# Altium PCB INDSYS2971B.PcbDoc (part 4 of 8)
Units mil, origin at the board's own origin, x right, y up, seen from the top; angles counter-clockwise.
Board outline 6450 x 5820 mil, 6 copper layers (Top Layer, Int1 (PGND), Int2 (AGND), Int3 (Signal), Int4 (PGND), Bottom Layer), stack 70.536 mil thick; 787 components, 431 nets, 2530 pads, 2497 vias.
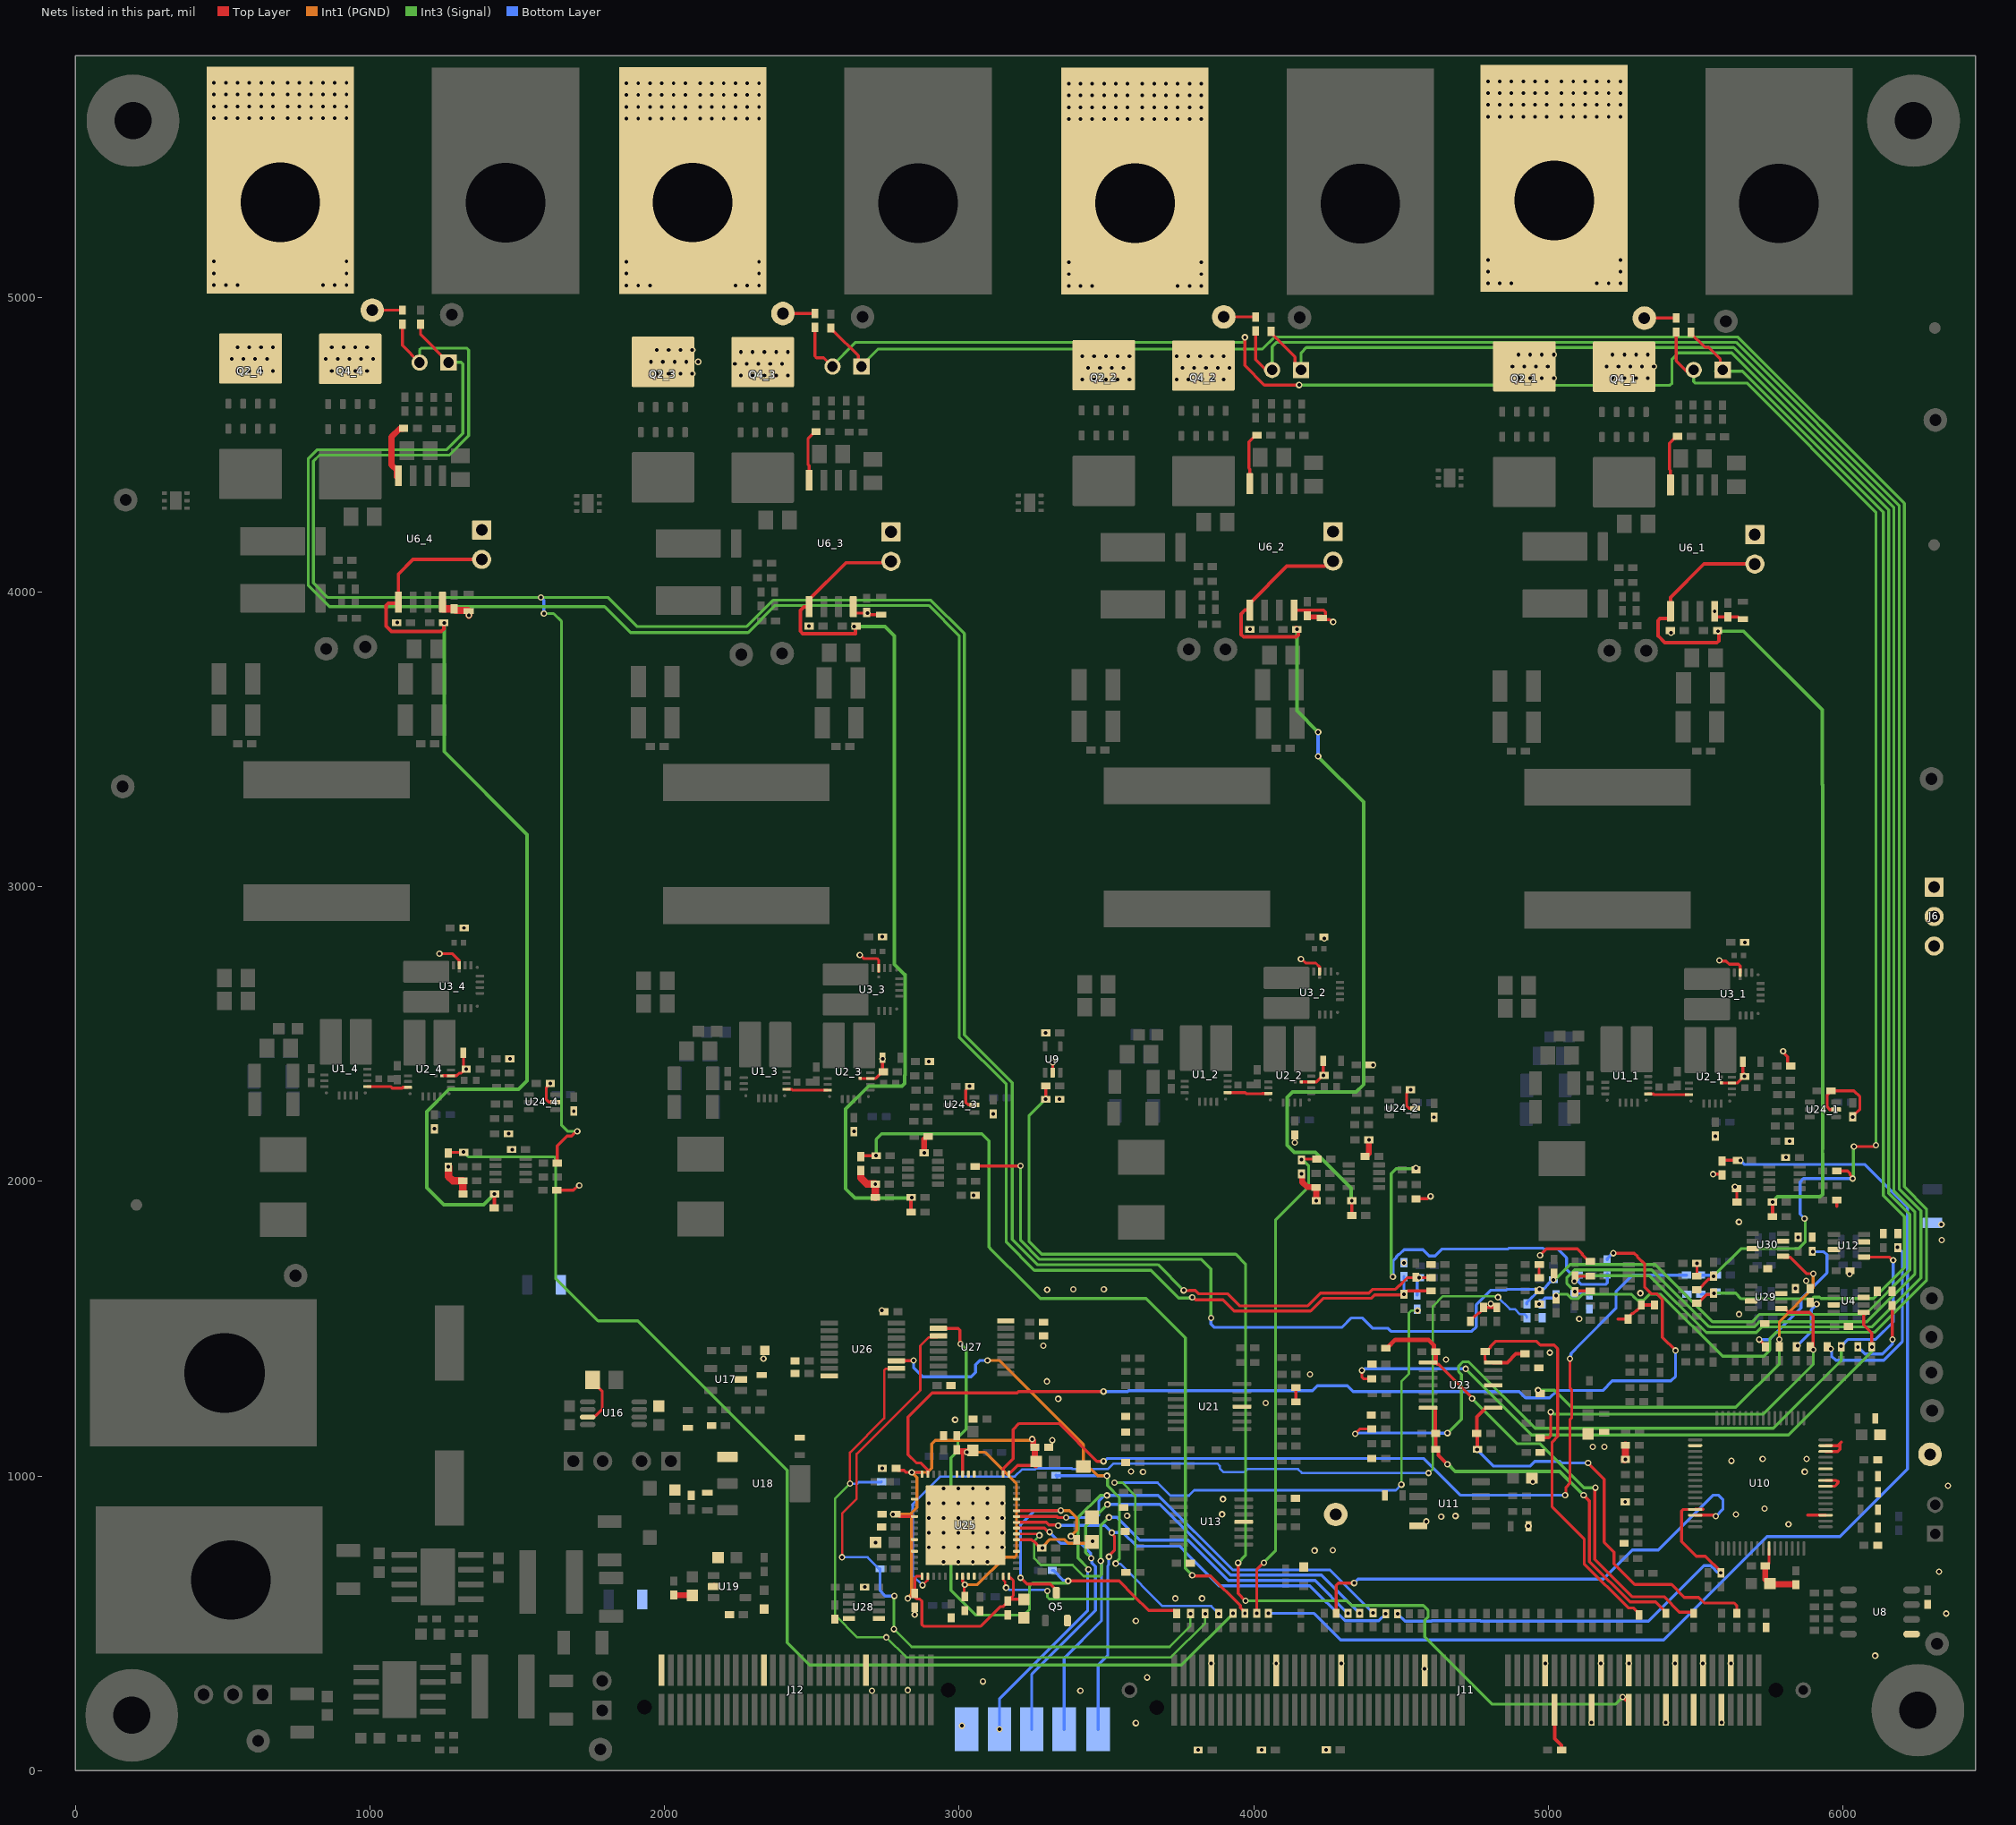
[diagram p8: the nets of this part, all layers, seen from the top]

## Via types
v1: diameter 22, hole 12.5, Top Layer to Bottom Layer, 873 vias
v2: diameter 22, hole 12, Top Layer to Bottom Layer, tented both sides, 788 vias
v3: diameter 22, hole 12, Top Layer to Bottom Layer, 586 vias
v4: diameter 22, hole 12.5, Top Layer to Bottom Layer, tented both sides, 249 vias
v5: diameter 24, hole 12, Top Layer to Bottom Layer, tented both sides, 1 vias

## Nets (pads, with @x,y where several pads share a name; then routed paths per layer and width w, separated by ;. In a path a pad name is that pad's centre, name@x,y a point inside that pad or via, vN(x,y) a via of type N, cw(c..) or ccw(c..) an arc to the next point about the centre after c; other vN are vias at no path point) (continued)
AGND: C19_1.2 C19_2.2 C19_3.2 C19_4.2 C20_1.1 C20_2.1 C20_3.1 C20_4.1 C22.2 C24_1.1 C24_2.1 C24_3.1 C24_4.1 C25.1 C27.2 C28_1.2 C28_2.2 C28_3.2 C28_4.2 C29_1.2 C29_2.2 C29_3.2 C29_4.2 C30_1.1 C30_2.1 C30_3.1 C30_4.1 C31_1.1 C31_2.1 C31_3.1 C31_4.1 C33_1.2 C33_2.2 C33_3.2 C33_4.2 C35.1 C36.1 C37.1 C38.1 C39.1 C40.1 C41.2 C43.2 C44.2 C45.2 C46.2 C47.2 C55.2 C56.2 C57.2 C58.2 C59.2 C60.2 C61.2 C62.2 C63.2 C64.1 C65.2 C66.1 C67.2 C68.1 C69.2 C70.2 C71.1 C83.1 C84.2 C85.2 C86.2 C87.2 C88.2 C89.2 C90.1 C91.2 C92.2 C93.1 C94.2 C95.2 C96.1 C98.1 C99.1 C104.1 C105.1 C109.1 C114_1.2 C114_2.2 C114_3.2 C114_4.2 C115_1.1 C115_2.1 C115_3.1 C115_4.1 C116.2 C117.1 C118.1 C119.1 C120.1 C121.1 C122.1 C123.1 C124.1 C125.1 C126.1 C127.1 C128.2 C129.1 C130.1 D1.1 D2.1 D3.1 D6.2 D7.2 J6.1 J6.2 J6.3 J9_1.1 J9_2.1 J9_3.1 J9_4.1 J11.7 J11.10 J11.13 J11.16 J11.19 J11.22 J11.29 J11.35 J11.38 J11.46 J11.47 J11.65 J11.83 J11.97 J11.111 J12.135 J12.157 J12.179 NT1_1.2 NT1_2.2 NT1_3.2 NT1_4.2 NT2_1.2 NT2_2.2 NT2_3.2 NT2_4.2 Q5.2 R10_1.2 R10_2.2 R10_3.2 R10_4.2 R11_1.2 R11_2.2 R11_3.2 R11_4.2 R16.1 R29_1.1 R29_2.1 R29_3.1 R29_4.1 R30_1.1 R30_2.1 R30_3.1 R30_4.1 R31_1.2 R31_2.2 R31_3.2 R31_4.2 R35_1.1 R35_2.1 R35_3.1 R35_4.1 R70.2 R80.2 R99.1 R101.1 R108.1 R109.1 R110.1 R114.2 R116.2 R117.2 R129.2 R130.1 R132.2 R134.2 R137.2 R139.1 R145.2 R148.2 R151.1 R156.2 R158.2 R162.1 R167.2 R168.2 R175.1 R181.1 R182.1 R189.1 R190.1 R221.1 R222.1 R224.1 R230.1 R243.1 R250.1 R254.1 R255.1 R256.1 R257.1 R258.2 R259.2 R260.2 TP7.1 TP15.1 TP16.1 U2_1.4 U2_2.4 U2_3.4 U2_4.4 U3_1.4 U3_2.4 U3_3.4 U3_4.4 U4.3 U4.7 U6_1.4 U6_2.4 U6_3.4 U6_4.4 U8.5 U9.2 U10.2 U10.26 U10.35 U10.40 U10.41 U10.43 U10.46 U10.47 U11.4 U12.3 U12.7 U13.11 U16.3 U17.2 U18.1 U19.2 U21.11 U23.11 U24_1.2 U24_2.2 U24_3.2 U24_4.2 U25.4 U25.11 U25.13 U25.23 U25.25 U25.26 U25.36 U25.45 U25.55 U25.56 U25.58 U25.65 U26.8 U27.8 U28.4 U28.5 U29.3 U29.7 U30.3 U30.7 | length 4589.8
  Top Layer w10: v2(1235.61,2773.14) 1279.05,2773.14 1302.77,2749.42 NT2_4.2@1302.77,2733.35 ; 1248.33,2359.71 1249.38,2358.65 1293.47,2358.65 1302.15,2367.33 1309.54,2367.33 1315.4,2373.19 1315.4,2374.17 1322.21,2380.98 v2(1326.14,2380.98) ; C20_4.1@1317,2387.79 C19_4.2@1317,2436.01 ; v2(1611.65,2332.2) 1598.46,2319 1598.46,2277.44 1606.98,2268.91 U24_4.2@1628.06,2268.91 ; R29_4.1@1633.62,1970.14 1690.35,1970.14 1706.21,1986 v2(1710,1986) ; U16.3@1738.62,1200.22 1758.42,1200.22 1762.28,1204.08 1765.33,1204.08 1788.26,1227 1788.26,1286.28 1755,1319.53 C91.2@1755,1326.03 ; U6_3.4@2640.39,3950.55 2640.39,3935.53 2647.2,3928.72 2688.16,3928.72 v2(2688.64,3928.24) 2688.64,3927.26 2692.2,3923.7 C30_3.1@2735.39,3923.7 ; v2(2662.53,2767.94) 2664.32,2767.94 2675.98,2756.27 2720.93,2756.27 2726.79,2750.41 U3_3.4@2726.79,2723.96 U3_3.4@2726.79,2712.95 ; NT1_3.2@2663.44,2350.14 2664.39,2349.18 U2_3.4@2698.65,2349.18 ; U2_3.4@2698.73,2349.26 2716.27,2349.26 2738.6,2371.59 C20_3.1@2742.54,2371.59 2739.81,2374.32 v2(2739.81,2415.75) ; v2(2739.52,2830.25) C24_3.1@2739.63,2830.14 ; v2(3035.67,2322.81) 3022.47,2309.61 3022.47,2268.05 3031,2259.52 U24_3.2@3052.08,2259.52 ; U9.2@3317.5,2369.43 v2(3317.5,2403.63) ; U6_2.4@4137,3938.94 4164.42,3938.94 4164.86,3938.5 4199.14,3938.5 4199.54,3938.9 4237.69,3938.9 4243.54,3933.04 C30_2.1@4243.54,3918.9 ; v2(4139.16,2132.12) R11_2.2@4139.16,2157.71 ; R158.2@4143.35,1251.83 R158.2@4143.62,1251.52 ; R167.2@4143.62,1300.14 R158.2@4143.62,1251.52 ; R158.2@4145,1250.14 R158.2@4143.62,1251.52 ; v2(4160.16,2754.32) 4163.41,2754.32 4176.76,2740.97 4210.84,2740.97 4223.4,2728.42 U3_2.4@4223.4,2712.35 ; NT1_2.2@4161.15,2337.34 4170.02,2337.34 4170.17,2337.5 4195.18,2337.5 U2_2.4@4195.26,2337.57 ; U2_2.4@4195.34,2337.65 4212.88,2337.65 4235.21,2359.98 v2(4237.18,2359.98) C20_2.1@4239.14,2359.98 4236.12,2363 C19_2.2@4236.12,2408.88 ; C30_2.1@4232,3918.9 4182,3918.9 4188.81,3912.09 C30_2.1@4232,3912.09 4237,3907.09 4258.07,3907.09 4266.24,3898.92 v2(4269.49,3898.92) v2(4269.49,3898.92) ; v2(4532.28,2311.2) 4519.08,2298 4519.08,2256.44 4527.6,2247.91 U24_2.2@4548.68,2247.91 ; R29_2.1@4551.23,1940.76 4552.05,1941.58 4589.69,1941.58 4597.13,1949.03 v2(4600.38,1949.03) ; C104.1@4734.05,1523.12 C104.1@4735.43,1524.5 ; C104.1@4735.43,1523.12 C104.1@4735.43,1524.5 ; R175.1@4780.43,1571.74 4780.43,1567.81 4765.74,1553.12 4762.57,1553.12 4752.57,1543.12 4750.11,1543.12 4735.43,1528.44 C104.1@4735.43,1524.5 ; R175.1@4781.8,1571.74 R162.1@4825.43,1571.74 ; C105.1@4969.05,1718.12 4969.05,1674.5 4970.43,1673.12 R156.2@4969.36,1672.96 ; v2(4972.23,1749.39) 4993.74,1770.9 5099.36,1770.9 5115.52,1754.74 5115.52,1751.41 5138.5,1728.44 R145.2@5142.44,1728.44 ; 5235.92,1532.4 5270.16,1532.4 C98.1@5270.92,1533.16 5270.92,1537.1 5285.6,1551.78 5288.77,1551.78 5298.77,1561.78 5301.23,1561.78 5317.44,1577.99 5317.44,1580.41 5317.44,1583.44 R151.1@5315.92,1580.41 ; v2(5416.97,3861.64) 5416.97,3859.8 5417.29,3859.8 5417.29,3869.18 R30_1.1@5416.97,3869.51 ; v2(5504.54,1721.78) 5502.44,1718.44 5504.68,1716.19 R134.2@5504.68,1678.44 ; v2(5559.53,2024.56) 5587.3,2024.56 R31_1.2@5590.34,2021.52 ; v2(5565,3934.94) 5565,3922.69 5571.81,3915.88 C31_1.1@5610,3915.88 5644.71,3915.88 5652.5,3908.09 C30_1.1@5660,3908.09 ; v4(5581.18,2750.4) 5583.48,2748.11 5603.25,2748.11 5614.38,2736.97 5645.54,2736.97 5651.4,2731.11 NT2_1.2@5651.4,2708.35 ; NT1_1.2@5588.05,2334.53 5589,2333.58 U2_1.4@5623.26,2333.58 5623.34,2333.65 5640.88,2333.65 5663.21,2355.98 C20_1.1@5667.14,2355.98 v2(5665.78,2357.35) 5660.66,2362.47 C19_1.2@5660.66,2406.14 ; C29_1.2@5640.51,1930.14 5639.96,1930.69 R35_1.1@5639.96,1975.38 R35_1.1@5642.47,1972.86 ; C55.2@5740,695.14 5741.3,695.14 5749.53,703.37 U10.26@5749.53,753.69 ; v2(5797.4,2441.79) 5797.4,2438.55 5812.62,2423.33 5812.62,2398.11 5819.43,2391.3 C114_1.2@5823.37,2391.3 ; 5880.09,866.88 U10.35@5941.46,866.88 ; U10.40@5941.46,965.3 5973.14,965.3 5982.7,974.86 5982.7,977.85 5985,980.14 ; U10.41@5941.46,984.99 5977.64,984.99 5981.75,980.88 5985,980.88 ; U10.46@5941.46,1083.41 5983.27,1083.41 5990,1090.14 5990,1110.14 ; U10.47@5941.46,1103.1 5982.95,1103.1 5990,1110.14 ; U24_1.2@5976.68,2243.91 5955.6,2243.91 5947.08,2252.44 5947.08,2294 C115_1.1@5960.28,2307.2 6038.05,2307.2 6058.15,2287.1 6058.15,2244.94 6042.73,2229.53 6040.28,2229.53 6033.46,2222.71 v2(6033.46,2218.78) ; R29_1.1@5979.23,1936.76 5979.42,1936.56 5979.42,1915.1 ; 5995,1115.14 5990,1110.14
  Top Layer w12: J11.46@5021.34,206.29 5021.34,108.81 5044.96,85.18 C37.1@5044.96,70.14 ; R151.1@5317.44,1580.41 R139.1@5360.92,1580.41
  Top Layer w20: C93.1@2031.2,596.13 2031.9,595.42 C92.2@2092.17,595.42 ; U19.2@2166.04,624.71 U19.2@2167.85,626.52 ; D3.1@2332.31,543.09 D3.1@2338.06,548.84 ; v2(2881.14,2096.75) 2881.14,2143.02 2890.45,2152.32 C28_3.2@2894.38,2152.32 ; R31_2.2@4162.34,2021.59 v2(4162.34,2025.52) 4164.15,2023.71 4164.15,1998.12 4181.08,1981.19 4210.15,1981.19 R35_2.1@4211.96,1979.38 4212.23,1979.11 4212.23,1934.42 v2(4212.51,1934.14) ; C33_2.2@4377.75,2085.14 4381.69,2085.14 4390.99,2094.45 v2(4390.99,2140.71) ; C55.2@5736.77,694.56 5736.77,649.24 C56.2@5750.87,635.14 ; C56.2@5752.52,634.48 C56.2@5750.87,635.14 ; R101.1@5841.02,630.93 5839.25,632.71 5757.44,632.71 5755,635.14 C56.2@5750.87,635.14
  Top Layer w25: U6_4.4@1246.1,3965.85 1246.1,3943.6 1246.79,3942.91 1284.91,3942.91 C31_4.1@1285,3942.82 1290.29,3937.53 1332.5,3937.53 C30_4.1@1335,3935.03 v2(1335,3921.72) ; v2(1265.34,2050.43) 1266.02,2049.74 1266.02,2016.69 1280.67,2002.04 1314.68,2002.04 R35_4.1@1314.96,2002.32 1315.23,2002.04 1315.23,1957.36 C29_4.2@1315.51,1957.08 ; R31_3.2@2665.73,2037.13 2665.73,2011.54 2685.59,1991.68 2714.66,1991.68 v2(2715.35,1990.99) 2715.62,1990.71 2715.62,1946.03 C29_3.2@2715.9,1945.75 ; R109.1@5260,1055.14 v2(5261.62,1056.76) R109.1@5261.93,1056.76 R110.1@5261.93,1104.56
  other v2: 3811.38,70.14 4026.38,70.14 4246.38,70.64 3009.68,152.04 3599.79,161.14 5146.9,162.98 5399.29,162.98 5588.27,162.98 2703.95,271.15 3411.2,271.23 2825.85,273.21 3080.43,302.45 3638.1,316.14 4580.39,344.99 3855.98,363.41 4076.46,363.41 4297.01,363.41 4989.84,363.41 5178.82,363.41 5273.6,363.41 5430.79,363.41 5525.28,363.64 5619.76,363.41 6110,390.13 3599.79,508.08 2849.09,529.52 6350.7,533.06 3733.94,584.67 3824.49,584.67 2679.44,622.93 6326.58,675.35 2946.54,707.93 2996.54,707.93 3046.54,707.93 3096.54,707.93 4206.7,746.97 4268.81,747.71 2896.54,757.93 2946.54,757.93 2996.54,757.93 3046.54,757.93 3096.54,757.93 3146.54,757.93 2716.41,774.29 2896.54,807.93 2946.54,807.93 2996.54,807.93 3046.54,807.93 3096.54,807.93 3146.54,807.93 5815.66,836.12 4586.11,845.74 2896.54,857.93 2946.54,857.93 2996.54,857.93 3046.54,857.93 3096.54,857.93 3146.54,857.93 4636.54,862.23 4685.17,864.33 3570.32,865.2 3892.59,870.14 5636.89,869.85 5734.36,889.33 2896.54,907.93 2946.54,907.93 2996.54,907.93 3046.54,907.93 3096.54,907.93 3146.54,907.93 5261.18,911.8 3895.58,921.85 2946.54,957.93 2996.54,957.93 3046.54,957.93 3096.54,957.93 6357.51,967.16 4947.16,981.14 3624.07,1013.71 5870.63,1014.51 3583.67,1015.52 2738.97,1026.11 5621.57,1051.27 5727.64,1057.91 5877.45,1057.91 5150.92,1099.05 5190.47,1099.05 3316.22,1121.16 2985.94,1190.89 4040.78,1247.64 3336.37,1262.08 3298.1,1321.39 4191.01,1345.14 4652.92,1394.83 2335.68,1398.27 5005.01,1418.65 3285.84,1442.07 5105.01,1533.16 5647.98,1549.24 2737.76,1562.54 4804.93,1584.62 5312.89,1620.37 3298.63,1631.84 3387.8,1633.84 3491.39,1633.84 5839.5,1636.08 5875.72,1662.65 6022.58,1684.9 4510,1723.77 6336.08,1800.82 5848.1,1810.18 6335.01,1853.89 5647.22,1862.27 3048.62,1952.37 5633.68,1981.73 5807.72,2081.15 1482.72,2108.08 5818.99,2136.71 5567.16,2153.71 1470.37,2161.71 2642.55,2169.32 1218.54,2178.71 4612.28,2217.66 3115.67,2229.27 1691.65,2238.66 3341.12,2278.72 4405,2395.3 2896.79,2406.91 1474.75,2416.3 3293.88,2503.72 5667.18,2811.46 4240,2825.14 1318.95,2860.14 3987,3873.5 2490.39,3885.11 1091.97,3896.44
  other v5: 4932.71,829.49
BATP_1: J7_1.1 Q2_1.5 Q2_1.6 Q2_1.7 Q2_1.8 Q2_1.9@4919,4766.07 Q4_1.5 Q4_1.6 Q4_1.7 Q4_1.8 Q4_1.9@5257.36,4765.07 R19_1.1 T3_1.1 TP5_1.1 | length 108.5
  Top Layer w10: TP5_1.1@5326.24,4930.14 R19_1.1@5434.69,4930.11
  other v1: 4898.39,4726.14 4938.39,4726.14 4978.39,4726.14 5018.39,4726.14 5218.39,4726.14 5258.39,4726.14 5298.39,4726.14 5338.39,4726.14 4878.39,4766.14 4918.39,4766.14 4958.39,4766.14 4998.39,4766.14 5198.39,4766.14 5238.39,4766.14 5278.39,4766.14 5318.39,4766.14 5358.39,4766.14 4898.39,4806.14 4938.39,4806.14 4978.39,4806.14 5018.39,4806.14 5218.39,4806.14 5258.39,4806.14 5298.39,4806.14 5338.39,4806.14
  other v3: 4795,5047.77 4835,5047.77 4875,5047.77 5165,5047.77 5205,5047.77 5245,5047.77 4795,5087.77 5245,5087.77 4795,5127.77 5245,5127.77 4795,5614.03 4835,5614.03 4875,5614.03 4915,5614.03 4955,5614.03 4995,5614.03 5045,5614.03 5085,5614.03 5125,5614.03 5165,5614.03 5205,5614.03 5245,5614.03 4795,5654.03 4835,5654.03 4875,5654.03 4915,5654.03 4955,5654.03 4995,5654.03 5045,5654.03 5085,5654.03 5125,5654.03 5165,5654.03 5205,5654.03 5245,5654.03 4795,5694.03 4835,5694.03 4875,5694.03 4915,5694.03 4955,5694.03 4995,5694.03 5045,5694.03 5085,5694.03 5125,5694.03 5165,5694.03 5205,5694.03 5245,5694.03 4795,5734.03 4835,5734.03 4875,5734.03 4915,5734.03 4955,5734.03 4995,5734.03 5045,5734.03 5085,5734.03 5125,5734.03 5165,5734.03 5205,5734.03 5245,5734.03
BATP_2: J7_2.1 Q2_2.5 Q2_2.6 Q2_2.7 Q2_2.8 Q2_2.9@3491,4770.07 Q4_2.5 Q4_2.6 Q4_2.7 Q4_2.8 Q4_2.9@3829.36,4769.07 R19_2.1 T3_2.1 TP5_2.1 | length 108.5
  Top Layer w10: TP5_2.1@3898.24,4934.14 R19_2.1@4006.69,4934.11
  other v1: 3418,4721.14 3458,4721.14 3498,4721.14 3538,4721.14 3578,4721.14 3738,4721.14 3778,4721.14 3818,4721.14 3858,4721.14 3898,4721.14 3438,4761.14 3478,4761.14 3518,4761.14 3558,4761.14 3758,4761.14 3798,4761.14 3838,4761.14 3878,4761.14 3918,4761.14 3418,4801.14 3458,4801.14 3498,4801.14 3538,4801.14 3578,4801.14 3738,4801.14 3778,4801.14 3818,4801.14 3858,4801.14 3898,4801.14
  other v3: 3371.97,5039.45 3411.97,5039.45 3451.97,5039.45 3741.97,5039.45 3781.97,5039.45 3821.97,5039.45 3371.97,5079.45 3821.97,5079.45 3371.97,5119.45 3821.97,5119.45 3371.97,5605.71 3411.97,5605.71 3451.97,5605.71 3491.97,5605.71 3531.97,5605.71 3571.97,5605.71 3621.97,5605.71 3661.97,5605.71 3701.97,5605.71 3741.97,5605.71 3781.97,5605.71 3821.97,5605.71 3371.97,5645.71 3411.97,5645.71 3451.97,5645.71 3491.97,5645.71 3531.97,5645.71 3571.97,5645.71 3621.97,5645.71 3661.97,5645.71 3701.97,5645.71 3741.97,5645.71 3781.97,5645.71 3821.97,5645.71 3371.97,5685.71 3411.97,5685.71 3451.97,5685.71 3491.97,5685.71 3531.97,5685.71 3571.97,5685.71 3621.97,5685.71 3661.97,5685.71 3701.97,5685.71 3741.97,5685.71 3781.97,5685.71 3821.97,5685.71 3371.97,5725.71 3411.97,5725.71 3451.97,5725.71 3491.97,5725.71 3531.97,5725.71 3571.97,5725.71 3621.97,5725.71 3661.97,5725.71 3701.97,5725.71 3741.97,5725.71 3781.97,5725.71 3821.97,5725.71
BATP_3: J7_3.1 Q2_3.5 Q2_3.6 Q2_3.7 Q2_3.8 Q2_3.9@1994.39,4781.68 Q4_3.5 Q4_3.6 Q4_3.7 Q4_3.8 Q4_3.9@2332.75,4780.68 R19_3.1 T3_3.1 TP5_3.1 | length 108.5
  Top Layer w10: TP5_3.1@2401.63,4945.75 R19_3.1@2510.05,4945.75
  other v1: 2258.57,4735.28 2298.57,4735.28 2338.57,4735.28 2378.57,4735.28 2418.57,4735.28 1973.78,4741.75 2013.78,4741.75 2053.78,4741.75 2093.78,4741.75 2238.57,4775.28 2278.57,4775.28 2318.57,4775.28 2358.57,4775.28 2398.57,4775.28 1953.78,4781.75 1993.78,4781.75 2033.78,4781.75 2073.78,4781.75 2113.78,4781.75 2258.57,4815.28 2298.57,4815.28 2338.57,4815.28 2378.57,4815.28 2418.57,4815.28 1973.78,4821.75 2013.78,4821.75 2053.78,4821.75 2093.78,4821.75
  other v3: 1870.39,5041.05 1910.39,5041.05 1950.39,5041.05 2240.39,5041.05 2280.39,5041.05 2320.39,5041.05 1870.39,5081.05 2320.39,5081.05 1870.39,5121.05 2320.39,5121.05 1870.39,5607.32 1910.39,5607.32 1950.39,5607.32 1990.39,5607.32 2030.39,5607.32 2070.39,5607.32 2120.39,5607.32 2160.39,5607.32 2200.39,5607.32 2240.39,5607.32 2280.39,5607.32 2320.39,5607.32 1870.39,5647.32 1910.39,5647.32 1950.39,5647.32 1990.39,5647.32 2030.39,5647.32 2070.39,5647.32 2120.39,5647.32 2160.39,5647.32 2200.39,5647.32 2240.39,5647.32 2280.39,5647.32 2320.39,5647.32 1870.39,5687.32 1910.39,5687.32 1950.39,5687.32 1990.39,5687.32 2030.39,5687.32 2070.39,5687.32 2120.39,5687.32 2160.39,5687.32 2200.39,5687.32 2240.39,5687.32 2280.39,5687.32 2320.39,5687.32 1870.39,5727.32 1910.39,5727.32 1950.39,5727.32 1990.39,5727.32 2030.39,5727.32 2070.39,5727.32 2120.39,5727.32 2160.39,5727.32 2200.39,5727.32 2240.39,5727.32 2280.39,5727.32 2320.39,5727.32
BATP_4: J7_4.1 Q2_4.5 Q2_4.6 Q2_4.7 Q2_4.8 Q2_4.9@594,4793.01 Q4_4.5 Q4_4.6 Q4_4.7 Q4_4.8 Q4_4.9@932.36,4792.01 R19_4.1 T3_4.1 TP5_4.1 | length 118
  Top Layer w10: TP5_4.1@998,4941.79 1013.07,4941.79 1028.36,4957.08 1074.99,4957.08 ; 1075.02,4957.05 R19_4.1@1109.69,4957.05
  other v1: 549.77,4751.14 589.77,4751.14 629.77,4751.14 669.77,4751.14 869.77,4751.14 909.77,4751.14 949.77,4751.14 989.77,4751.14 529.77,4791.14 569.77,4791.14 609.77,4791.14 649.77,4791.14 849.77,4791.14 889.77,4791.14 929.77,4791.14 969.77,4791.14 1009.77,4791.14 549.77,4831.14 589.77,4831.14 629.77,4831.14 669.77,4831.14 869.77,4831.14 909.77,4831.14 949.77,4831.14 989.77,4831.14
  other v3: 470,5042.38 510,5042.38 550,5042.38 840,5042.38 880,5042.38 920,5042.38 470,5082.38 920,5082.38 470,5122.38 920,5122.38 470,5608.65 510,5608.65 550,5608.65 590,5608.65 630,5608.65 670,5608.65 720,5608.65 760,5608.65 800,5608.65 840,5608.65 880,5608.65 920,5608.65 470,5648.65 510,5648.65 550,5648.65 590,5648.65 630,5648.65 670,5648.65 720,5648.65 760,5648.65 800,5648.65 840,5648.65 880,5648.65 920,5648.65 470,5688.65 510,5688.65 550,5688.65 590,5688.65 630,5688.65 670,5688.65 720,5688.65 760,5688.65 800,5688.65 840,5688.65 880,5688.65 920,5688.65 470,5728.65 510,5728.65 550,5728.65 590,5728.65 630,5728.65 670,5728.65 720,5728.65 760,5728.65 800,5728.65 840,5728.65 880,5728.65 920,5728.65
BATSN1: J10_1.1 R22_1.2 R70.1 R136.1 R138.2 R220.1 | length 4367.9
  Top Layer w10: R22_1.2@5484.69,4881.49 5484.69,4877.55 5530.96,4831.28 5544.25,4831.28 5583.72,4791.81 5583.72,4762.7 J10_1.1@5592.17,4754.25 ; R136.1@5504.54,1586.78 5508.48,1586.78 5538.16,1616.47 5560.92,1616.47 R138.2@5560.92,1620.18 ; R138.2@5560.92,1620.41 v2(5562.85,1620.41) 5564.78,1620.41 R138.2@5565,1620.18
  Int3 (Signal) w10: v2(5562.85,1620.41) 5636.31,1620.41 5655.19,1601.53 5895.35,1601.53 5901.27,1607.45 5921.04,1607.45 5926.19,1602.31 6104.92,1602.31 6209.25,1706.64 6209.25,1880.61 6206.32,1883.54 6137.76,1952.11 6137.76,4271.56 5659.17,4750.14 5596.27,4750.14 J10_1.1@5592.17,4754.25 ; J10_1.1@5568.43,4750.14 J10_1.1@5592.17,4750.14
  Bottom Layer w10: R70.1@5518.39,1616.74 5556.82,1616.74 5560.48,1620.41 v2(5562.85,1620.41)
BATSN2: J10_2.1 R22_2.2 R147.1 R149.2 R223.1 R258.1 | length 6610.3
  Top Layer w10: R22_2.2@4056.69,4885.49 4056.69,4881.55 4140.43,4797.81 J10_2.1@4140.43,4754.14 ; R149.2@5093.95,1628.44 R147.1@5142.44,1628.44
  Int3 (Signal) w10: J10_2.1@4160.93,4754.14 4160.93,4812.07 4178.87,4830.02 5629.85,4830.02 6173.5,4286.36 6173.5,1966.92 6245,1895.42 6245,1686.52 6082.12,1523.64 5717.28,1523.64 5699.41,1505.77 5550.55,1505.77 5548.67,1507.64 5543.8,1507.64 5351.3,1700.14 5089.52,1700.14 5063.08,1673.7 5063.08,1653.25 v2(5090.92,1625.41)
  Bottom Layer w10: v2(5090.92,1625.41) 5090.92,1623.28 5093.52,1620.68 5133.19,1620.68 R258.1@5140,1613.87
BATSN3: J10_3.1 R22_3.2 R159.1 R161.2 R225.1 R259.1 | length 8239
  Top Layer w10: R22_3.2@2563.95,4896.35 2563.95,4892.41 2570.76,4885.6 2574.7,4885.6 2657.85,4802.45 2657.85,4776.39 J10_3.1@2668.49,4765.75
  Int3 (Signal) w10: J10_3.1@2665.18,4765.75 2724.45,4825.02 4029.6,4825.02 4070.34,4865.77 5644.66,4865.77 6209.25,4301.17 6209.25,1981.73 6284.12,1906.85 6284.12,1662.57 6109.45,1487.89 5775.01,1487.89 5752.46,1465.35 5752.46,1426.89 5731.85,1406.27 5592.26,1406.27 5381.79,1616.74 5343.03,1616.74 5322.78,1596.49 5303,1596.49 5289.01,1610.48 5289.01,1610.89 5283.16,1616.74 5116.02,1616.74 5100.81,1601.53 5081.03,1601.53 5065.82,1616.74 v2@5026.16,1616.74
  Bottom Layer w10: v2(4969.05,1583.12) 4989.54,1603.61 5019.35,1603.61 5026.16,1610.42 v2(5026.16,1612.39)
BATSN4: J10_4.1 R22_4.2 R172.1 R173.2 R227.1 R260.1 | length 7561.5
  Top Layer w10: R22_4.2@1171.42,4909.84 1171.42,4874.26 J10_4.1@1266.43,4779.25 ; v2(3791.14,1606.06) 3794.39,1606.06 3802.7,1597.74 3895.58,1597.74 3933.64,1559.68 4192.7,1559.68 4236.1,1603.08 4398.93,1603.08 4410.71,1614.86 4510,1614.86 4510,1620.68 4516.81,1627.49 4522.04,1627.49 4522.67,1628.12 4557.24,1628.12 R172.1@4601.8,1628.12
  Int3 (Signal) w10: J10_4.1@1266.43,4779.25 1267.32,4780.14 1309.14,4780.14 1315,4774.29 1315,4538.13 1260.4,4483.53 821.28,4483.53 789.77,4452.02 789.77,4023.31 861.93,3951.14 1795.72,3951.14 1884.23,3862.63 2283.42,3862.63 2375.57,3954.78 2896.97,3954.78 3000,3851.75 3000,2489.96 3160,2329.96 3160,1793.18 3255.17,1698.02 3650.82,1698.02 3745.08,1603.76 3788.84,1603.76 v2(3791.14,1606.06)
  Bottom Layer w10: v2(4510,1616.74) R260.1@4510,1676.52
BATSP1: J10_1.2 R19_1.2 R24_1.1 R133.2 R135.1 R235.1 R239.1 | length 4261.3
  Top Layer w10: R19_1.2@5434.69,4882.87 5434.69,4785.46 J10_1.2@5470,4750.14 ; R135.1@5504.54,1631.78 5508.48,1631.78 5544.11,1667.41 R133.2@5554.11,1667.41 ; R24_1.1@5979.23,2035.14 6015.85,2035.14 6024.55,2026.44 6024.55,2022.15 6033.87,2012.83 v2(6033.87,2009.59) ; v2(6037.5,2117.9) 6107.34,2117.9 v2(6112.31,2122.87)
  Int3 (Signal) w10: J10_1.2@5493.74,4754.25 5493.74,4714.36 5498.39,4709.71 5674.32,4709.71 6112.31,4271.73 v2(6112.31,2122.87) ; v2(5560.92,1678.16) 5654.43,1771.68 5849.7,1771.68 5872.34,1794.32 5872.34,1852.49 5872.3,1852.54 5872.3,1871.19 v2(5870,1873.49) ; v2(6033.87,2009.59) 6035.69,2011.4 6035.69,2116.09 v2(6037.5,2117.9)
  Bottom Layer w10: R239.1@5516.31,1681.9 5560.68,1681.9 5560.92,1681.66 v2(5560.92,1678.16) ; v2(5870,1873.49) 5854.71,1888.78 5854.71,1997.84 5866.45,2009.59 v2(6033.87,2009.59)
BATSP2: J10_2.2 R19_2.2 R24_2.1 R144.2 R146.1 R237.1 R248.1 | length 8046.2
  Top Layer w10: R19_2.2@4006.69,4886.87 4006.69,4789.46 J10_2.2@4042,4754.14 ; v2(5088.91,1661.4) 5089.91,1662.4 5089.91,1676.42 5091.29,1677.79 5141.79,1677.79 R146.1@5142.44,1678.44
  Int3 (Signal) w10: J10_2.2@4062.5,4754.14 4062.5,4832.64 4077.75,4847.89 5637.25,4847.89 6191.38,4293.77 6191.38,1974.32 6265,1900.7 6265,1672.5 6098.27,1505.77 5724.73,1505.77 5705.91,1486.94 5536.87,1486.94 5343.61,1680.2 5107.71,1680.2 v2(5088.91,1661.4) ; v2(4472.71,1676.52) 4472.71,1679.77 4466.34,1686.13 4466.34,2025.88 4483.6,2043.15 4548.43,2043.15 v2(4550.43,2045.14)
  Bottom Layer w10: v2(4472.71,1676.52) 4472.87,1676.69 4472.87,1730.43 4485.31,1742.88 4485.31,1744.85 4492.86,1752.39 4494.83,1752.39 4510.54,1768.1 4574.21,1768.1 4595.79,1746.52 4615.57,1746.52 4639.44,1770.39 4862.93,1770.39 4865.81,1773.26 4982.12,1773.26 4984.99,1770.39 5032.35,1770.39 5062.48,1740.25 5062.48,1700.74 5076.3,1686.92 5096.77,1686.92 R237.1@5101.79,1681.9 5101.79,1661.4 ; v2(5088.91,1661.4) 5101.79,1661.4 ; R248.1@5200,1686.52 5200,1655.95 5194.14,1650.09 5112.57,1650.09 5101.79,1660.88 5101.79,1661.4
BATSP3: J10_3.2 R19_3.2 R24_3.1 R155.2 R157.1 R244.1 R249.1 | length 10925.1
  Top Layer w10: R19_3.2@2510.08,4898.48 2510.08,4801.07 2515.34,4795.81 2539.93,4795.81 2569.99,4765.75 J10_3.2@2570.07,4765.75 ; R24_3.1@3054.62,2050.75 3055.85,2051.98 3207.22,2051.98 v2(3208.45,2053.22) ; v2(3970,4865.14) 3970,4768.96 4035.92,4703.05 v2(4154.16,4703.05) ; v2(5017.53,1666.09) 5018.68,1667.24 5018.68,1686.57 R155.2@5019.83,1687.71
  Int3 (Signal) w10: J10_3.2@2566.76,4765.75 2648.9,4847.89 3964.14,4847.89 3967.7,4851.45 3967.7,4862.85 v2(3970,4865.14) ; v2(3208.45,2053.22) 3208.45,1799.57 3272.66,1735.36 3822.37,1735.36 3855,1702.73 v2(3855,1536.65) ; v2(4154.16,4703.05) 4887.73,4703.05 4888.5,4702.27 5413.37,4702.27 5420,4708.9 5420,4791.46 5440.69,4812.14 5622.44,4812.14 6155.63,4278.96 6155.63,1959.51 6227.13,1888.02 6227.13,1699.24 6076.48,1548.6 5716.96,1548.6 5692,1523.64 5557.95,1523.64 5363.58,1718.02 5073.94,1718.02 v2@5022.02,1666.09
  Bottom Layer w10: v2(3855,1536.65) 3855,1515.4 3865.58,1504.82 4300.45,1504.82 4332.29,1536.65 4367.89,1536.65 4402.92,1501.62 4455.25,1501.62 4465.72,1491.14 4740.87,1491.14 4755.55,1505.82 4755.55,1580.59 4805.68,1630.72 4856.86,1630.72 4859.72,1633.58 v2(4970.27,1633.58) ; R249.1@4927.36,1584.4 4927.36,1588.34 4970.27,1631.24 v2(4970.27,1633.58) ; v2(5017.53,1666.09) 5013.6,1666.09 4998.91,1651.41 4998.91,1648.95 4985.84,1635.87 4972.57,1635.87 v2(4970.27,1633.58)
BATSP4: J10_4.2 R8.1 R19_4.2 R24_4.1 R166.2 R170.1 R246.1 | length 9784.7
  Top Layer w10: R19_4.2@1109.69,4909.81 1109.69,4837.57 J10_4.2@1168,4779.25 ; R24_4.1@1635.28,2061.89 1635.28,2120.71 1668.23,2153.67 1683.9,2153.67 1700.37,2170.14 v2(1703.62,2170.14) ; v2(3762.29,1629.93) 3763.38,1628.84 3780.15,1628.84 3781.25,1629.93 3801.03,1629.93 3812.41,1618.55 3910.64,1618.55 3951.64,1577.56 4183.72,1577.56 4227.12,1620.96 4391.53,1620.96 4404.38,1633.8 4481.3,1633.8 4492.86,1645.37 4493.45,1645.37 4521.21,1673.12 4550.43,1673.12 v2(4562.06,1673.12) R170.1@4601.8,1673.12
  Int3 (Signal) w10: J10_4.2@1168,4779.25 1168,4822.2 1173.86,4828.06 1328.7,4828.06 1335,4821.75 1335,4530.91 1269.09,4465 828.03,4465 807.64,4444.61 807.64,4030.71 856.6,3981.75 v2(1580,3981.75) 1809.48,3981.75 1809.48,3980.09 1906.17,3883.4 2278.9,3883.4 2368.16,3972.66 2904.37,3972.66 3017.87,3859.16 3017.87,2497.36 3180,2335.23 3180,1802.74 3265.26,1717.49 3674.73,1717.49 v2(3762.29,1629.93) ; v2(1590,3927.27) 1622.73,3927.27 1650,3900 1650,2190.14 1670,2170.14 v2(1703.62,2170.14)
  Bottom Layer w10: v2(1580,3981.75) 1590,3971.75 v2(1590,3927.27) ; R246.1@4550.43,1674.5 4550.43,1671.25 4554.67,1667.01 R8.1@4554.67,1613.79
Board_temp: C41.1 J11.30 R77.1 | length 4039.3
  Top Layer w10: v2(3293.88,2279.83) R77.1@3293.88,2323.72 ; v2(3947.08,705.08) 3947.08,601.48 v2(3972.29,576.27) ; v2(5252.6,249.57) 5273.31,228.86 J11.30@5273.31,206.29
  Int3 (Signal) w10: v2(3293.88,2279.83) 3236.94,2222.9 3236.94,1796.36 3280.06,1753.23 3939.2,1753.23 3972.29,1720.14 3972.29,730.28 v2(3947.08,705.08) ; v2(3972.29,576.27) 4316.99,576.27 4333.01,560.25 4575.52,560.25 4590.85,544.91 4590.85,543.5 4592.18,542.17 4592.18,522.39 4580.39,510.6 4580.39,453.43 4808.03,225.8 5228.83,225.8 v2(5252.6,249.57)
BUSY_INT: R68.1 U10.14 | length 1671.8
  Top Layer w10: R68.1@4280,533.77 4280,628.65 4287.87,636.52 v2(4341.05,636.52) ; U10.14@5498.54,866.88 v2@5562.25,866.88
  Bottom Layer w10: v2(4341.05,636.52) 4354.67,650.14 5187.07,650.14 5285.84,748.91 5373.35,748.91 5559.28,934.83 5579.05,934.83 5593.04,920.85 5593.04,887.08 v2(5569.16,863.21)
CSn: R63.1 R92.2 U10.13 | length 1557
  Top Layer w10: R63.1@4487.91,532.67 v2(4488.31,532.28) ; 5525.8,887.08 5525.35,886.64 5498.62,886.64 U10.13@5498.54,886.56 5498.46,886.48 5458.77,886.48 5452.91,880.62 5452.91,777.04 5502.26,727.69 5533.65,727.69 5585.98,675.35 v2(5585.98,671.41)
  Bottom Layer w10: v2(4488.31,532.28) 4513.18,507.4 4603.33,507.4 4604.84,508.91 4768.94,508.91 4770.79,507.06 4934.89,507.06 4935.24,507.4 5340.85,507.4 5528.73,695.29 5551.86,695.29 5565.84,681.3 5565.84,679.76 5571.89,673.71 5583.69,673.71 v2(5585.98,671.41)
CVSEL1: R195.1 R240.2 U26.11 | length 1903.4
  Top Layer w10: U26.11@2786.82,1391 2787.45,1391.63 2844.36,1391.63 v2(2844.99,1392.26)
  Int3 (Signal) w10: v2(3501.98,1000.73) 3503.37,999.33 3503.37,967.72 3543.8,927.29 3543.8,718.66 3531.44,706.3 v2(3531.44,703.05)
  Int1 (PGND) w10: v2(3096.54,1392.26) 3135.97,1392.26 3421.59,1106.64 3421.59,1048.83 3469.69,1000.73 v2(3501.98,1000.73)
  Bottom Layer w8: v2(3531.44,703.05) 3532.46,702.03 3546.94,702.03 3690.48,558.49 3855.49,558.49 v2(3881.08,532.9)
  Bottom Layer w10: v2(2844.99,1392.26) 2844.99,1368.02 2876.26,1336.75 3041.03,1336.75 3055.63,1351.35 3055.63,1377.53 3070.35,1392.26 v2(3096.54,1392.26) ; R240.2@3329.21,1002.16 3330.65,1000.73 v2(3501.98,1000.73) ; R240.2@3331.67,996.02 R240.2@3333.51,997.86
CVSEL2: R197.1 R242.2 U26.10 | length 2450.3
  Top Layer w8: v2(2629.17,974.13) 2629.17,1079.74 2745.42,1195.99 2745.42,1359.22 2750.11,1363.91 2785.32,1363.91 U26.10@2786.82,1365.41
  Int3 (Signal) w8: v2(2629.17,974.13) 2578.76,923.71 2578.76,528.21 2654.5,452.46 v2(2752.45,452.46) 2820.6,384.32 3718.93,384.32 3835,500.39 v2(3835,532.9)
  Bottom Layer w8: v2(2629.17,974.13) 2653.72,974.13 2658.68,979.09 2734.9,979.09 R242.2@2736.38,980.57
CVSEL3: R196.2 R252.2 U27.11 | length 2395.2
  Top Layer w8: v2(2602.58,724.34) 2602.58,872.69 2652.04,922.15 2652.04,1075.09 2867.86,1290.91 2867.86,1442.07 2896.46,1470.67 2924.91,1470.67 U27.11@2929.76,1475.53
  Int3 (Signal) w8: v2(2780,592.72) 2778.62,591.34 v2(2778.62,480.14) 2838.62,420.14 3714.33,420.14 3785.24,491.05 v2(3785.24,532.9)
  Bottom Layer w8: v2(2602.58,724.34) 2688.92,724.34 2719.63,693.63 2719.63,692.95 2727.44,685.14 R252.2@2731.38,685.14
  Bottom Layer w10: R252.2@2731.38,685.14 2731.38,610.62 2749.28,592.72 v2(2780,592.72)
CVSEL4: R198.2 R253.2 U27.10 | length 1998.5
  Top Layer w10: U27.10@2929.76,1501.12 2996.29,1501.12 3002.15,1495.26 3002.15,1450.69 v2(3004.44,1448.4) ; v2(3370.12,643.65) 3543.2,643.65 3593.94,592.92 3643.21,543.65 3731.79,543.65 3738.6,536.84 R198.2@3738.6,532.9
  Int3 (Signal) w10: v2(3004.44,1448.4) 3024.11,1428.73 3024.11,1159.27 2995.87,1131.03 2995.87,1085.79 2972.04,1061.95 2972.04,611.75 3055.77,528.02 3219.53,528.02 3238.7,547.19 3238.7,626.14 3249.09,636.52 v2@3370.12,636.52
  Bottom Layer w10: R253.2@3316.22,679.83 3320.16,679.83 3354.04,645.95 3367.82,645.95 v2(3370.12,643.65)
DAC1: R239.2 U25.50 | length 3186.6
  Top Layer w10: U25.50@3149.49,1006.16 3149.76,1006.44 3149.76,1025.27 3183.25,1058.75 3183.25,1157.85 3203.57,1178.17 3339.38,1178.17 3467.78,1049.77 v2(3490.12,1049.77) ; v2(5057.52,934.83) 5060.2,937.51 5060.2,961.74 5073.52,975.06 5073.52,1190.92 5079.42,1196.83 5079.42,1293.25 5073.82,1298.85 v2(5073.82,1398.51)
  Bottom Layer w10: v2(3490.12,1049.77) 3492.35,1049.77 3501.98,1059.4 4578.27,1059.4 4702.84,934.83 v2(5057.52,934.83) ; v2(5073.82,1398.51) 5076.12,1400.81 5076.12,1409.23 5077.26,1410.37 5077.26,1416.09 5110.03,1448.85 5229.93,1568.75 5229.93,1625.35 5236.07,1631.49 5236.07,1632 5285.97,1681.9 R239.2@5469.07,1681.9
DAC2: R248.2 U25.63 | length 3527.9
  Top Layer w10: U25.63@2893.58,1006.16 2893.31,1006.44 2893.31,1020.33 2869.23,1044.4 2854.4,1044.4 2826.53,1072.27 2826.53,1200.44 2908.11,1282.02 3196.77,1282.02 3201.46,1286.7 v2(3490.12,1286.78) ; v2(5220.9,1756.27) 5291.68,1756.27 5303.18,1744.77 5303.18,1742.36 5317.17,1728.37 5319.57,1728.37 5327.02,1720.93 5327.02,1642.02 5350.72,1618.32 5368.77,1618.32 5387.51,1599.58 5387.51,1470.78 v2(5432.34,1425.95)
  Int1 (PGND) w10: v2(5220.9,1756.27) v2@5222.56,1757.93
  Bottom Layer w10: v2@3490.76,1286.78 3572.12,1286.78 3574.73,1289.39 4199.44,1289.39 4216.46,1306.41 4317.7,1306.41 4337.34,1286.78 4901.77,1286.78 4923.04,1265.51 5004.99,1265.51 5029.62,1290.14 5184.82,1290.14 5217.4,1322.73 5416.3,1322.73 5432.34,1338.76 v2(5432.34,1425.95) ; R248.2@5200,1733.77 5200,1737.7 5222.37,1760.08 5222.37,1757.74 v2(5220.9,1756.27)
DAC3: R249.2 U25.18 | length 3102.8
  Top Layer w8: v2(2875.36,629.02) 2892.86,646.5 2892.86,658.98 U25.18@2893.58,659.7
  Int3 (Signal) w8: v2(4593.79,1010.12) 4608.12,1024.46 4608.12,1575.96 4642.41,1610.25 4817.89,1610.25 4818.61,1609.52 4826.9,1609.52 v2(4829.58,1606.85)
  Bottom Layer w8: v2(2875.36,629.02) 2842.4,661.97 2842.4,904.7 2935.86,998.15 3189.26,998.15 3213.77,1022.66 3258.12,1022.66 3261.3,1025.84 3382.01,1025.84 3384.26,1023.6 3504.97,1023.6 3523.9,1042.52 3876.05,1042.52 3884.6,1033.97 3884.6,1026.05 3898,1012.65 3966.8,1012.65 3977.75,1023.6 4150.12,1023.6 4163.59,1010.12 v2(4593.79,1010.12) ; v2(4829.58,1606.85) 4870.12,1566.3 4876.49,1566.3 4886.15,1566.3 4903.55,1548.9 4919.55,1548.9 4927.36,1541.09 R249.2@4927.36,1537.15
DAC4: R8.2 U25.31 | length 2582.4
  Top Layer w8: U25.31@3149.49,659.7 3150.21,658.98 3150.21,646.5 3156.38,640.34 3156.38,623.8 v2(3159.06,621.12)
  Int3 (Signal) w8: v2(3299.31,609.53) 3299.31,589.36 3306.2,582.47 3590.94,582.47 3597.82,589.36 3597.82,782.52 3597.42,782.93 3597.42,934.11 3553.92,977.61 v2(3527.24,977.61) ; v2(4501.37,970.96) 4501.37,1320.95 4526.87,1346.45 4526.87,1553 4535.4,1561.52 v2(4556.28,1561.52)
  Bottom Layer w8: v2(3159.06,621.12) 3162.84,621.12 3170.08,613.88 3300.15,613.88 3300.15,610.36 v2(3299.31,609.53) ; v2(3527.24,977.61) 3673.55,977.61 3717.76,933.4 3780.06,933.4 3798.37,951.71 4482.11,951.71 v2(4501.37,970.96)
DAC_ALARM: D6.1 R231.1 U25.38 | length 282.7
  Top Layer w10: U25.38@3194.76,783.72 3245.08,783.72 3248.66,780.14 3251.76,780.14 3276.55,755.36 v2(3282.45,755.36)
  Int1 (PGND) w10: v2@3286.81,763.07 3308.46,784.72 3356.66,784.72 3369.48,771.89 3442.35,771.89 3449.55,779.09 v2(3452.79,779.09)
DAC_CS: R67.1 TP22.1 U25.39 | length 2200.5
  Top Layer w8: U25.39@3194.04,802.68 U25.39@3194.76,803.4 3264.21,803.4 3268.74,798.87 v2(3272.53,798.87)
  Int3 (Signal) w8: v2(3272.53,798.87) 3272.53,797.8 3254.9,780.16 3254.9,720.06 3277.15,697.8 3385.13,697.8 3422.9,660.02 3478.48,660.02 3483.16,664.71 3483.16,709.11 v2(3480.71,711.56)
  Int3 (Signal) w10: v2(3480.71,711.56) 3480.71,831.65 v2(3508.59,859.54)
  Bottom Layer w10: TP22.1@3356.54,140.14 3356.54,381.45 3483.16,508.08 3483.16,705.86 3480.71,708.31 v2(3480.71,711.56) ; v2(3508.59,859.54) 3535.61,859.54 3612.71,782.43 3777.15,782.43 3914.14,645.45 4208.31,645.45 v2(4320,533.77)
DAC_PICO: R65.1 TP20.1 U25.41 | length 2098.3
  Top Layer w10: U25.41@3194.76,842.77 3295.83,842.77 3304.89,833.72 3334.62,833.72 v2(3336.37,831.97) ; v2(3508.59,725.97) 3508.59,729.21 3527.05,747.68 3527.05,796.07 3518.39,804.73 v2(3518.39,807.93)
  Bottom Layer w10: v2(3336.37,831.97) 3494.36,831.97 v2(3518.39,807.93) 3555.62,807.93 3603.27,760.28 3604.91,761.92 3748.73,761.92 3765.19,745.46 3765.19,743.71 3881.32,627.58 4191.01,627.58 4309.7,508.89 4424.92,508.89 v2(4448.31,532.28) ; TP20.1@3471.54,140.14 3471.54,358.52 3504.58,391.57 3504.58,694.97 3507.56,697.95 3507.56,724.94 v2(3508.59,725.97)
DAC_POCI: R194.1 TP21.1 U25.42 | length 2423.9
  Top Layer w10: U25.42@3194.76,862.46 3331.66,862.46 3335.22,858.91 v2(3363.35,858.91)
  Int3 (Signal) w10: v2(3438.66,682.9) 3438.66,685.82 3403.63,720.85 3403.63,859.01 3478.73,934.11 v2(3501.98,934.11)
  Bottom Layer w10: v2(3137.1,140.14) 3137.1,244.54 3436.36,543.79 3436.36,680.6 v2(3438.66,682.9) ; v2(3363.35,858.91) 3465.68,858.91 3473.88,867.11 3473.88,915.09 3490.61,931.82 3499.68,931.82 v2(3501.98,934.11) 3676.03,934.11 3928.94,681.2 4259.17,681.2 v2(4405,535.37)
DAC_RESET: Q5.3 R228.1 U25.43 | length 797.6
  Top Layer w10: U25.43@3194.76,882.14 3270.18,882.14 3270.81,882.78 v2(3345.23,882.78) ; v2(3208.45,654.7) 3229.75,633.4 3309.2,633.4 3323.19,619.41 3323.19,618.94 3330,612.13 Q5.3@3330,603.77 ; v2(3379.37,795.77) 3380.08,795.06 3392.3,795.06 3399.11,788.25 R228.1@3399.11,784.31
  Int1 (PGND) w10: v2(3345.23,882.78) 3374.8,882.78 3399.35,858.24 3399.35,815.74 v2(3379.37,795.77)
  Bottom Layer w10: v2(3208.45,654.7) 3208.45,835.56 3255.66,882.78 v2(3345.23,882.78)
DAC_SCLK: R66.1 TP8.1 U25.40 | length 2212.8
  Top Layer w10: U25.40@3194.76,823.09 3290.24,823.09 3303.48,809.85 v2(3306.73,809.85)
  Int3 (Signal) w10: v2(3448.52,720.69) 3428.92,740.29 3428.92,829.21 v2(3503.37,903.67)
  Bottom Layer w10: TP8.1@3246.54,140.14 3246.54,327.48 3462.53,543.48 3462.53,692.79 3450.81,704.5 3450.81,718.4 3446.22,722.99 3446.22,738.62 3412.95,771.89 3344.68,771.89 v2(3306.73,809.85) ; v2(3503.37,903.67) 3681.2,903.67 3921.54,663.33 4230.36,663.33 v2(4359.92,533.77)
DAC_VCC: C116.1 C117.2 C118.2 C119.2 C120.2 C121.2 R207.2 U25.7 U25.17 U25.32 U25.49 U25.64 | length 2079.3
  Top Layer w10: C117.2@2785.19,870.15 2789.13,870.15 2796.81,862.46 U25.7@2848.31,862.46 ; C119.2@2786.21,1026.11 2793.03,1019.3 2812.82,1019.3 2819.84,1012.28 v2(2838.52,1012.28) 2873.62,1012.28 2873.9,1012 U25.64@2873.9,1006.16 ; v2@2834.82,590.39 2842.27,590.39 C118.2@2849.09,597.2 ; U25.17@2873.9,659.7 2854.94,659.7 2849.09,653.85 C118.2@2849.09,601.14 C118.2@2849.09,597.2 ; C121.2@3165,575.51 C121.2@3170.01,580.53 ; C121.2@3168.9,575.48 3150.32,556.89 3140.2,556.89 3073.29,489.98 2879.63,489.98 2873.77,495.84 2873.77,574.98 2866.23,582.52 2855.82,582.52 2849.09,589.25 C118.2@2849.09,597.2 ; C121.2@3168.9,581.64 C116.1@3220,581.64 ; U25.32@3169.17,659.7 3169.17,653.17 3169.45,652.89 3175.98,652.89 3183.98,644.9 3183.98,594.5 C121.2@3175.75,586.26 ; U25.49@3169.17,1006.16 3169.17,1012.7 3169.45,1012.97 3175.98,1012.97 3198.54,1035.52 R207.2@3261.1,1035.52
  Top Layer w20: v2(3247.7,1125.35) 3247.7,1124.81 3251.12,1121.39 3251.12,1099.1 3252.93,1097.29 C120.2@3256.86,1097.29 3256.86,1039.76 R207.2@3261.1,1035.52
  Int1 (PGND) w10: v2(2775.35,870.14) 2833.81,870.14 2838.52,865.44 ; v2(2825.85,584.67) 2825.85,587.92 2838.52,600.59 2838.52,865.44 ; v2@3243.8,1121.16 2918.65,1121.16 2906.33,1108.85 2906.33,1026.41 2892.2,1012.28 2838.57,1012.28 2856.32,994.52 2856.32,892.68 2838.52,874.87 2838.52,865.44
DAC_VEE: C125.2 C126.2 R241.1 U25.24 U25.57 | length 873.7
  Top Layer w10: U25.24@3011.69,659.7 3011.97,659.43 3011.97,641.74 3019.18,634.54 v2(3019.18,631.29) ; U25.57@3011.69,1006.16 3011.69,1080.78 ; v2@3016.69,621.12 3016.69,592.96 C126.2@3019.27,590.38
  Top Layer w20: C125.2@2992.01,1089.49 2992.01,1085.55 2993.82,1083.74 3022.71,1083.74 3025.5,1080.96 v2(3026.04,1080.96) 3026.42,1081.34 3040.64,1081.34 R241.1@3046.54,1087.24
  Int1 (PGND) w10: v2(3019.18,631.29) 3061.93,631.29 3155.31,724.66 3188.96,724.66 3194.82,730.52 3194.82,973.03 3086.89,1080.96 v2(3026.04,1080.96)
EN_SSR1: R31_1.1 R32_1.1 R72.1 | length 4033.4
  Top Layer w10: R31_1.1@5590.34,2068.77 5593.01,2071.44 v2(5652.65,2071.44)
  Bottom Layer w10: v2(4050,533.77) 4204.82,533.77 4295.3,443.29 5391.62,443.29 5742.4,794.07 5990.42,794.07 6220,1023.65 6220,1912.69 6075.41,2057.27 5666.82,2057.27 v2(5652.65,2071.44)
EN_SSR2: R31_2.1 R32_2.1 R73.1 | length 1677.9
  Top Layer w10: v2(4010,533.77) 4010,681.29 v2(4034.45,705.73) ; R31_2.1@4162.34,2072.77 4165.01,2075.44 R32_2.1@4214.81,2075.44
  Int3 (Signal) w10: v2(4034.45,705.73) 4073.87,745.16 4073.87,1868.75 4186.21,1981.08 4186.21,2053.22 4183.28,2056.15 4168.29,2071.14 ccw(c4163.65,2066.5) 4163.65,2073.06 cw(c4163.65,2083.06) 4162.34,2073.15 v2@4162.34,2073.06
  other v2: 4162.34,2073.88
EN_SSR3: R31_3.1 R32_3.1 R74.1 | length 2718.4
  Top Layer w10: R31_3.1@2665.73,2084.37 2668.4,2087.05 R32_3.1@2718.2,2087.05 ; v2(3791.14,663.33) 3793.44,661.03 3853.8,661.03 3954.69,560.14 3954.69,553.02 3970,537.7 v2(3970,533.77)
  Int3 (Signal) w10: v2(2718.2,2088.17) 2718.2,2142.7 2736.77,2161.27 3077.15,2161.27 3101.02,2137.4 3101.02,1777 3104.25,1773.77 3104.25,1773.1 3232.95,1644.4 3233.62,1644.4 3275.49,1602.53 3634.94,1602.53 3768.44,1469.02 3768.44,686.03 v2(3791.14,663.33)
EN_SSR4: R31_4.1 R32_4.1 R75.1 | length 4040.8
  Top Layer w10: R31_4.1@1265.34,2096.44 1267.27,2098.38 R32_4.1@1317.81,2098.38
  Int3 (Signal) w10: v2(1317.81,2099.49) 1333.76,2083.54 1624.14,2083.54 1630,2077.68 1630,1670.65 1774.13,1526.52 1908.52,1526.52 2416.13,1018.92 2416.13,433.87 2491.98,358.02 3754.25,358.02 v2(3930,533.77)
FaultN_1: J9_1.2 R23_1.2 R26_1.1 R33_1.1 U6_1.1 | length 3094.3
  Top Layer w12: R23_1.2@5574.72,3869.5 v2(5576.98,3867.25) 5579.24,3864.99 5579.24,3835.14 5572.21,3828.11 5396.28,3828.11 5372.37,3852.01 5372.37,3902.98 5379.4,3910.01 5409.19,3910.01 5415,3915.82 U6_1.1@5415,3934.94 5415,3981.83 5528.51,4095.34 J9_1.2@5701.4,4095.34 ; R26_1.1@5761.02,1880.14 v2(5761.02,1930.14)
  Int3 (Signal) w12: v2(5576.98,3867.25) 5662.9,3867.25 5930,3600.14 5930,3346.84 5931.56,3345.28 5931.56,2110.52 5931.13,2110.09 5931.13,2094.45 5931.56,2094.02 5931.56,1956.05 5922.97,1947.46 5778.34,1947.46 v2(5761.02,1930.14)
FaultN_2: J9_2.2 R23_2.2 R26_2.1 R33_2.1 U6_2.1 | length 3107.7
  Top Layer w12: R23_2.2@4144.61,3879.76 4144.61,3875.62 v2(4146.72,3873.5) ; R23_2.2@4151.24,3868.99 4151.24,3854.85 4144.21,3847.82 3965.51,3847.82 3957.38,3855.95 3957.38,3926.32 3970,3938.94 U6_2.1@3987,3938.94 3987,3962.56 4112.58,4088.14 J9_2.2@4242,4088.14 ; R26_2.1@4333.02,1884.14 v2(4333.02,1934.14)
  Int3 (Signal) w12: v2(4146.72,3873.5) 4146.72,3597.42 v2(4219,3525.14) ; v2(4219,3442.64) 4219,3441.15 4372.82,3287.32 4372.82,2328.57 4347.54,2303.29 4131.45,2303.29 4113.07,2284.91 4113.07,2123.02 4137.34,2098.76 4209.25,2098.76 4331.11,1976.89 4331.11,1936.06 v2(4333.02,1934.14)
  Bottom Layer w12: v2(4219,3442.64) v2(4219,3525.14)
FaultN_3: J9_3.2 R23_3.2 R26_3.1 R33_3.1 U6_3.1 | length 3129.6
  Top Layer w12: v2(2643.82,3883.4) 2647.6,3879.61 2647.6,3859.43 2468.9,3859.43 2460.77,3867.55 2460.77,3937.92 2473.39,3950.55 U6_3.1@2490.39,3950.55 2490.39,3974.17 2615.97,4099.74 J9_3.2@2745.39,4099.74 ; R26_3.1@2836.41,1895.75 R33_3.1@2836.41,1944.73
  Int3 (Signal) w12: v2(2643.82,3883.4) 2747.72,3883.4 2780,3851.12 2780,2737.07 2815.19,2701.88 2816.26,2700.81 2816.26,2361.29 2815.19,2360.22 2815.19,2332.64 2806.02,2323.47 2692.66,2323.47 2614.58,2245.39 2614.58,1974.69 2646.24,1943.03 2837.14,1943.03 v2(2838.84,1944.73)
FaultN_4: J9_4.2 R23_4.2 R26_4.1 R33_4.1 U6_4.1 | length 3365.6
  Top Layer w12: U6_4.1@1090,3961.88 1062.03,3961.88 1055,3954.85 1055,3884.26 1072.61,3866.65 1241.74,3866.65 1249.72,3874.63 R23_4.2@1249.72,3896.44 1250.53,3896.44 v2(1251.24,3895.73) ; U6_4.1@1096.1,3965.85 1096.1,4061.07 1146.11,4111.08 1328.99,4111.08 1329.12,4110.94 J9_4.2@1378.99,4110.94 ; R26_4.1@1421.38,1910.14 1421.8,1910.57 1421.8,1956.66 v2(1422.23,1957.08)
  Int3 (Signal) w12: v2(1251.24,3895.73) 1251.24,3458.76 1533.46,3176.54 1533.46,2342.14 1503.49,2312.17 1267.81,2312.17 1192.63,2237 1192.63,1978.69 1250.79,1920.53 1385.68,1920.53 v2(1422.23,1957.08)
Gate_1: R25_1.1 U6_1.8 | length 179.6
  Top Layer w10: U6_1.8@5415,4364.07 5415,4413.36 5411.7,4416.66 5411.7,4505.89 5427.87,4522.07 5431.81,4522.07 R25_1.1@5438.62,4528.88
Gate_2: R25_2.1 U6_2.8 | length 179.6
  Top Layer w10: U6_2.8@3987,4368.07 3987,4417.36 3983.7,4420.66 3983.7,4509.89 4006.69,4532.88 R25_2.1@4010.62,4532.88
Gate_3: R25_3.1 U6_3.8 | length 179.6
  Top Layer w10: U6_3.8@2490.39,4379.68 2490.39,4428.97 2487.09,4432.27 2487.09,4521.5 2510.08,4544.48 R25_3.1@2514.01,4544.48
Gate_4: R25_4.1 U6_4.8 | length 196.2
  Top Layer w20: U6_4.8@1090,4391.01 1090,4414.63 1072.61,4432.02 1072.61,4527.02 1099.59,4554 1111.81,4554 R25_4.1@1113.62,4555.81
HO_1: U1_1.2 U2_1.10 | length 139.8
  Top Layer w10: U1_1.2@5339.02,2296.93 5339.1,2296.85 5357.18,2296.85 5359.82,2294.21 U2_1.10@5477.59,2294.21 U2_1.10@5477.67,2294.13
HO_2: U1_2.2 U2_2.10 | length 140.3
  Top Layer w10: U1_2.2@3911.02,2300.93 3971.11,2300.93 3974.58,2297.45 4028.95,2297.45 4029.7,2298.2 U2_2.10@4049.59,2298.2
HO_3: U1_3.2 U2_3.10 | length 139.7
  Top Layer w10: U1_3.2@2414.42,2312.54 2414.49,2312.46 2432.08,2312.46 2434.72,2309.81 U2_3.10@2552.98,2309.81
HO_4: U1_4.2 U2_4.10 | length 141.8
  Top Layer w10: U1_4.2@990.4,2321.93 1069.69,2321.93 1074.94,2316.68 1109.23,2316.68 1111.76,2319.2 U2_4.10@1128.97,2319.21
IOCP1: C111.1 R37.2 R184.1 U23.1 | length 1646.1
  Top Layer w10: U23.1@4592.31,1384.79 U23.1@4612.2,1384.79 ; U23.1@4616.92,1384.79 4622.75,1378.96 4627.97,1378.96 4741.37,1265.56 v4(4741.37,1262.91) ; v4(5160,960.14) 5157.83,957.97 5157.83,716.9 5284.58,590.14 5393.11,590.14 5445.31,537.94 5489.6,537.94 R37.2@5493.78,533.77
  Top Layer w15: C111.1@4448.31,1433.66 4452.25,1433.66 4480.86,1462.27 4593.22,1462.27 4612.28,1443.22 4612.28,1425.87 4616.59,1421.56 R184.1@4617.99,1421.56 4617.99,1387.08 4615.7,1384.79 U23.1@4612.2,1384.79
  Int3 (Signal) w10: v4(4741.37,1262.91) 4894.98,1109.3 4972.22,1109.3 5121.38,960.14 v4(5160,960.14)
IOCP2: C110.1 R39.2 R183.1 U23.7 | length 1308.1
  Top Layer w10: 5138.95,914.88 5139.95,913.88 5139.95,709.5 5277.18,572.27 5364.72,572.27 5399.29,537.7 R39.2@5399.29,533.77
  Top Layer w12: U23.7@4592.31,1231.25 4616.01,1231.25 4616.9,1230.36 4616.9,1145.54 R183.1@4617.99,1144.44 C110.1@4617.99,1090.43 4621.25,1090.43 4627.06,1084.62 4627.06,1070.48 v2(4657.99,1039.56) ; v4(5120,934.83) 5138.95,915.88 5138.95,914.88
  Int3 (Signal) w12: v2(4657.99,1039.56) 4660.17,1039.56 4684.04,1015.69 5039.15,1015.69 v4(5120,934.83)
IOCP3: C113.1 R38.2 R192.1 U23.8 | length 1469.4
  Top Layer w10: v4(5135,1044.04) 5135.16,1044.04 5189.68,989.52 5189.68,775.36 5223.19,741.86 5223.19,702.09 5293.71,631.57 5418.57,631.57 5462.13,588.02 5510.57,588.02 5529.8,568.79 5631.35,568.79 5640,560.14 R38.2@5640,533.77
  Top Layer w12: v4(4758.27,1089.27) 4758.58,1089.58 4758.58,1143.3 R192.1@4757.44,1144.44 4757.44,1200.51 4788.18,1231.25 U23.8@4812.79,1231.25
  Bottom Layer w10: v4(4758.27,1089.27) 4813.99,1033.56 4937.67,1033.56 4953.87,1049.77 5039.95,1049.77 5045.67,1044.04 v4(5135,1044.04)
IOCP4: C112.1 R40.2 R191.1 U23.14 | length 1500.4
  Top Layer w10: U23.14@4812.79,1384.79 4788.18,1384.79 4786.29,1386.68 4786.29,1395.06 4785.25,1396.1 C112.1@4785.25,1422.91 4792.06,1429.72 4796,1429.72 4803.87,1437.59 4803.87,1440.05 4821.12,1457.3 4960.33,1457.3 4973.11,1444.52 5019.29,1444.52 5032.07,1431.73 5032.07,1134.17 5012.99,1115.09 5012.99,895.18 5122.08,786.09 5122.08,702.09 5271.9,552.27 5288.86,552.27 5308.43,532.7 R40.2@5308.43,528.77
  Top Layer w12: U23.14@4812.79,1384.79 4860.28,1384.79 4890.23,1414.74 R191.1@4920.59,1414.74
IoutN1: R16.2 R81.1 | length 273.7
  Top Layer w10: R16.2@6167.06,1579.02 6168.1,1577.99 6168.1,1464.8 v2(6169.14,1463.77)
  Bottom Layer w10: v2(6051.02,1438.18) 6074.9,1414.3 6135.17,1414.3 6168.5,1447.63 6168.5,1463.13 v2(6169.14,1463.77)
IoutN2: R85.1 R255.2 | length 626.1
  Bottom Layer w10: v2(5959.21,1431.8) 5961.89,1429.12 5961.89,1407.07 5976.06,1392.9 6139.18,1392.9 6202.13,1455.85 6202.13,1760.29 v2(6185.38,1777.04)
IoutN3: R87.1 R256.2 | length 191.8
  Top Layer w10: R256.2@5889.5,1588.83 5894.76,1583.58 v2(5911.16,1583.58)
  Bottom Layer w10: v2(5846.34,1442.47) 5893.46,1489.59 5893.46,1564.51 5911.16,1582.2 v2(5911.16,1583.58)
IoutN4: R91.1 R257.2 | length 492.5
  Top Layer w10: v2(5715.75,1463.07) 5716.45,1463.07 5737.4,1442.12 R91.1@5737.4,1438.18 ; R257.2@5896.45,1762.94 v2(5898.22,1761.16)
  Bottom Layer w10: v2(5715.75,1463.07) 5750.18,1463.07 5787.97,1500.86 5857.71,1570.6 5857.71,1601.35 5946.04,1689.68 5946.04,1751.33 5936.21,1761.16 v2(5898.22,1761.16)
IoutP1: R78.1 R180.1 U4.5 | length 2145.5
  Top Layer w10: v2(4367.53,1358.07) 4367.53,1335.58 4373.39,1329.72 R180.1@4400.83,1329.72 ; U4.5@6071.25,1555.26 6071.25,1512.22 6098.27,1485.2 v2(6098.27,1438.18)
  Int3 (Signal) w10: v2(4719.54,1363.72) 4943.8,1139.46 5815.42,1139.46 6097.82,1421.86 6097.82,1437.73 v2(6098.27,1438.18)
  Bottom Layer w10: v2(4367.53,1358.07) 4370.78,1358.07 4376.43,1363.72 v2(4719.54,1363.72)
IoutP2: R83.1 R179.1 U12.5 | length 2695.3
  Top Layer w10: v2(4344.43,1143.3) 4360.84,1159.72 R179.1@4400.83,1159.72 ; U12.5@6072.11,1743.18 6157.33,1743.18 6167.76,1732.75 v2(6171.01,1732.75)
  Int3 (Signal) w10: v2(4657.99,1145.54) 4705.04,1192.59 4705.04,1344.46 4695.67,1353.83 4695.67,1373.61 4709.65,1387.59 4729.43,1387.59 4955.38,1161.64 5764.18,1161.64 5994.65,1392.11 v2(5994.65,1440.06)
  Bottom Layer w10: v2(4344.43,1143.3) 4346.72,1145.6 4355.21,1145.6 4355.88,1146.27 4621.19,1146.27 4621.93,1145.54 v2(4657.99,1145.54) ; v2(5994.65,1440.06) 6018.36,1463.77 6112.01,1463.77 6171.01,1522.76 v2(6171.01,1732.75)
IoutP3: R86.1 R187.1 U29.5 | length 1366.3
  Top Layer w10: R187.1@4972.95,1129.72 5002.34,1129.72 5008.2,1135.58 v2(5008.2,1216.95) ; U29.5@5791.06,1568.06 5802.87,1568.06 5815.66,1555.26 5887.6,1555.26 5899.6,1543.27 v2(5899.6,1428.34)
  Int3 (Signal) w10: v2(5008.2,1216.95) 5011.45,1216.95 5018.26,1210.14 5730.17,1210.14 5900,1379.97 5900,1427.93 v2(5899.6,1428.34)
IoutP4: R90.1 R188.1 U30.5 | length 1410.9
  Top Layer w10: R90.1@5784.65,1438.18 v2(5784.65,1463.77) ; U30.5@5796.81,1745.92 5800.67,1742.06 5822.15,1742.06 5877.68,1686.52 v2(5899.6,1686.52)
  Int3 (Signal) w10: v2(4965.07,1291.14) 5021.42,1291.14 5079.42,1233.14 5636.71,1233.14 5784.65,1381.08 v2(5784.65,1463.77)
  Int1 (PGND) w10: v2(5784.65,1463.77) 5784.65,1523.46 5899.6,1638.4 v2(5899.6,1686.52)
